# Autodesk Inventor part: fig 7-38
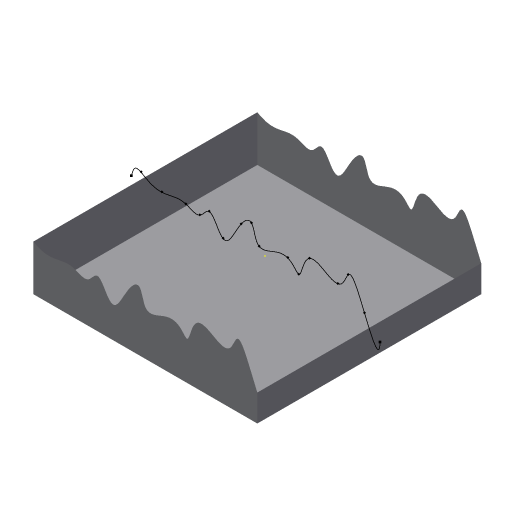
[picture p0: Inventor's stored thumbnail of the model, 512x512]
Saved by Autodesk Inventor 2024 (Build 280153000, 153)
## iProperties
Shininess: 64.0
Length Units: 11269
Angle Units: 11279
Time Units: 11290
Mass Units: 11283
Length Display Precision: 3
Angle Display Precision: 2
Compacted: True
Part Number: fig 7-38
Document SubType Name: Modeling
Created: 2002-12
Designer: deepak
Density: 1 g/cm^3
Material: Generic
Appearance: Default
Density: 0.0
Volumn: 0.0
Area: 0.0
PropertySet Name: Model Information
Control State: 0
Master: False
Checked Out: False
Author: cadcim
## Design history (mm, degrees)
sketch "Sketch1"
  geometry: L1 (-32.188, 30.089)-(27.812, 30.089); L2 (27.812, 30.089)-(27.812, -29.911); L3 (27.812, -29.911)-(-32.188, -29.911); L4 (-32.188, -29.911)-(-32.188, 30.089)
  constraints: 8 end point, 2 parallel, 1 horizontal, 1 perpendicular
  dimensions: "d0" = 60 distance of L1.start L1.end; "d1" = 60 distance of L3.end L1.start
extrude "Extrusion1" new body sketch "Sketch1" stored distance "d2" = 20; taper "d3" = 0 deg
sketch "Sketch2"
  geometry: 17 further points
  constraints: 17 other
extrude_surface "ExtrusionSrf1" sketch "Sketch2" dims "d4" = 70, "d5" = 0
split "Split1"
delete_face "Delete Face1"
body "Srf1"
node "Sketch5"
sketch "Sketch6"
  geometry: 1 further point
body "Srf2"
